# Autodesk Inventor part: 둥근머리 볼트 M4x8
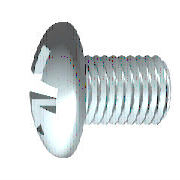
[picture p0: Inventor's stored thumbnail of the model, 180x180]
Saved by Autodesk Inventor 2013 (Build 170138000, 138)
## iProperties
Created: 2012-02
Part Number: 둥근머리 볼트 M4x8
Material: 강철, 연강
Description: 십자 오목 머리 나사
Document SubType Name: Modeling
Standard: KS B 1023
Designer: mduedu
Standards Organization: KS
Language: ko-KR
Size Designation: A  M 4 x 8 - H
Categories: <MemberInstance><Categories><Category DisplayName="조임쇠" InternalName="e4da775c-781d-43d5-af7c-5136215cf5a6" Mnemonic="FSTN"><Category DisplayName="볼트" InternalN
Density: 1 g/cm^3
IsCustomPart: 1
Author: mduedu
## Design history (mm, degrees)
workplane "Work Plane3"
sketch "스케치2"
  geometry: L1 (-5.374, 0)-(5.374, 0) reference; L2 (0, -5.374)-(0, 5.374) reference; L3 (0, 2.3)-(0, 0); L4 (0, 0)-(2.3, 0); L5 (0, 0)-(2.714, 2.714); L6 (0.311, 2.279)-(0.392, 0.703); L7 (2.279, 0.311)-(0.703, 0.392); L8 (0.311, -2.279)-(0.392, -0.703); L9 (2.279, -0.311)-(0.703, -0.392); L10 (-0.311, 2.279)-(-0.392, 0.703); L11 (-2.279, 0.311)-(-0.703, 0.392); L12 (-2.279, -0.311)-(-0.703, -0.392); L13 (-0.311, -2.279)-(-0.392, -0.703); A1 r 0.69 centre (0, 0) between (0.69, 0) and (0, 0.69); A2 r 2.3 centre (0, 0) between (2.3, 0) and (2.279, 0.311); A3 r 2.3 centre (0, 0) between (0.311, 2.279) and (0, 2.3); A4 r 2.3 centre (0, 0) between (2.279, 0.311) and (0.311, 2.279); A5 r 2.3 centre (0, 0) between (0, -2.3) and (0.311, -2.279); A6 r 2.3 centre (0, 0) between (0.311, -2.279) and (2.279, -0.311); A7 r 2.3 centre (0, 0) between (2.279, -0.311) and (2.3, 0); A8 r 2.3 centre (0, 0) between (-2.279, 0.311) and (-2.3, 0); A9 r 2.3 centre (0, 0) between (-0.311, 2.279) and (-2.279, 0.311); A10 r 2.3 centre (0, 0) between (0, 2.3) and (-0.311, 2.279); A11 r 2.3 centre (0, 0) between (-2.3, 0) and (-2.279, -0.311); A12 r 2.3 centre (0, 0) between (-2.279, -0.311) and (-0.311, -2.279); A13 r 2.3 centre (0, 0) between (-0.311, -2.279) and (0, -2.3); A14 r 0.805 centre (0, 0) between (0.805, 0) and (0, 0.805); A15 r 0.328 centre (0.72, 0.72) between (0.392, 0.703) and (0.703, 0.392); A16 r 0.328 centre (0.72, -0.72) between (0.703, -0.392) and (0.392, -0.703); A17 r 0.328 centre (-0.72, 0.72) between (-0.703, 0.392) and (-0.392, 0.703); A18 r 0.328 centre (-0.72, -0.72) between (-0.392, -0.703) and (-0.703, -0.392); 1 further point
  constraints: 38 point on circle, 22 end point, 19 symmetric about line, 18 centre point, 4 coincident, 3 collinear, 3 point on line, 3 tangent, 1 perpendicular, 21 other
  dimensions: "d4" = 45 deg angle of L5 L4; "d5" = 1.38 diameter of A1 (= 0.3 x SDM); "d6" = 4.6 diameter of A4 (= SDM); "d7" = 0.3115 distance from line of L6.start L3 (= 0.5 x SBR); "d14" = 1.61 diameter of A14 (= 0.35 x SDM)
extrude "슬롯" join sketch "스케치2" taper "d15" = 5 deg; stored distance "d54" = 10
revolve "절단부" stored, may be unused: angle "d56" = 90 deg
revolve "본체" stored, may be unused: angle "d18" = 90 deg
workplane "Work Plane1"
body "Solid1"
sketch "스케치1"
  geometry: L1 (8, 0)-(8, 2); L2 (8, 2)-(1.4, 2); L3 (3.962, 5.08)-(3.962, 5.08); L4 (-3.1, 0)-(-3.1, 3.729); L5 (-2.744, 2.122)-(-1.498, 1.501); L6 (-1.498, 1.501)-(-0.7, 0); L7 (-0.7, 0)-(8, 0); L8 (-5.687, 0)-(10.281, 0) reference; L9 (0, -1.016)-(0, 6.096) reference; L10 (-2.744, 2.122)-(-3.1, 2.3); L11 (-1.846, 3.839)-(-3.1, 3.729); L12 (-1.846, 3.839)-(0, 4); L13 (0, 4)-(0, 1.785); L14 (0, 1.785)-(0.971, 1.785); L15 (0.971, 1.785)-(1.4, 2); L16 (1.4, 2)-(0, 2); A1 r 6.5 centre (3.4, 0) between (-1.846, 3.839) and (-3.1, 0)
  constraints: 28 end point, 5 point on line, 4 collinear, 4 point on circle, 3 parallel, 2 perpendicular, 1 centre point, 1 horizontal, 1 tangent
  dimensions: "d1" = 4 diameter of L2 L7 (= GD); "d2" = 2.4 distance from line of L6.end L4 (= STI); "d11" = 4.6 diameter of L10.end L7 (= SDM); "d12" = 62 deg angle of L6 L7; "d13" = 26.5 deg angle of L5 L7; "d17" = 8 diameter of L12.end L7 (= KOD); "d19" = 5 deg angle of L12 L7 (= KEWI); "d20" = 3.1 distance between parallel lines of L4 L13 (= KOH); "d21" = 6.5 radius of A1 (= KR); "d23" = 3.5705 diameter of L14 L7 (= BDM); "d24" = 6.6 distance of L1.end L2.end (= GEL); "d25" = 0.42941 horizontal distance of L14.end L2.end (= GAL); "d28" = 8 distance between parallel lines of L1 L13 (= NLG)
fillet "모깎기1" dims "d29" = 1.6 (= RR)
fillet "모깎기2" dims "d16" = 0.1246 (= 0.2 x SBR)
feature "스레드" dims "d8" = 6.6 (= GEL), "d9" = 0
chamfer "모따기1" distance "d26" = 0.42941 (= -0.5 x SPD + 0.5 x GD); stored, may be unused: second distance "d27" = 0.42952 (computed from GUL), angle "d78" = 45 deg
other parameters: "GD" = 4 (= NND) [user parameter; used in 2 equation terms], "NLG" = 8 [user parameter; used in 1 equation term], "GEL" = 6.6 [user parameter; used in 2 equation terms], "KOD" = 8 [user parameter; used in 1 equation term], "KOH" = 3.1 [user parameter; used in 2 equation terms], "SDM" = 4.6 [user parameter; used in 4 equation terms], "STI" = 2.4 [user parameter; used in 1 equation term], "SBR" = 0.623 [user parameter; used in 2 equation terms], "GAL" = 0.42941 (= 0.61345 x PTC) [user parameter; used in 1 equation term], "SPD" = 3.14117 (= NND - 1.2269 x PTC) [user parameter; used in 1 equation term], "KEWI" = 5 deg [user parameter; used in 1 equation term], "d3" = -3.1 (= -KOH), "d10" = 0, "KR" = 6.5 [user parameter; used in 1 equation term], "BDM" = 3.5705 [user parameter; used in 1 equation term], "GUL" = 0.42941 (= 0.61345 x PTC) [user parameter; used in 1 equation term], "RR" = 1.6 [user parameter; used in 1 equation term], "d79" = 0, "d80" = 0, "PTC" = 0.7 [user parameter; used in 5 equation terms], "THREADDIA" = 4 [user parameter; used in 1 equation term], "TOA" = 30 deg [user parameter], "TPU" = 14.28571 (computed from PTC) [user parameter], "NND" = 4 [user parameter; used in 2 equation terms], "GD1" = 3.14117 (= THREADDIA - 1.2269 x PTC) [user parameter]
